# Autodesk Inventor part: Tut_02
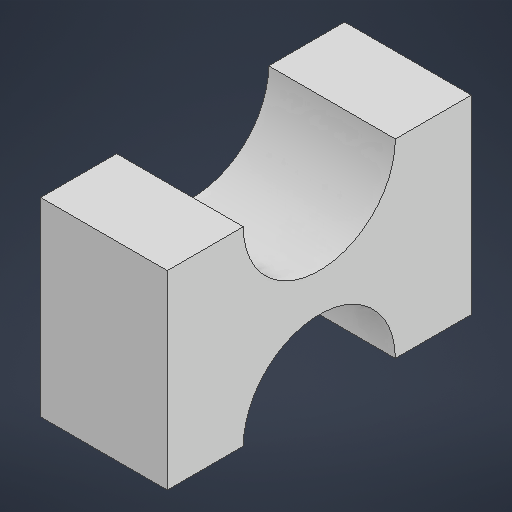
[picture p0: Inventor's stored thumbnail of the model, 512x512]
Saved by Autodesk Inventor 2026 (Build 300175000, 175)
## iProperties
Created: 2022-07
Part Number: Tut_02
Material: Generic
Document SubType Name: Modeling
Designer: LENOVO-CADCIM
Density: 1 g/cm^3
Appearance: Default
Author: LENOVO-CADCIM
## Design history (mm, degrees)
sketch "Sketch5"
  geometry: L1 (0, 0)-(0, 12); L2 (0, 0)-(12, 0); L3 (0, 0)-(0, -12); L4 (0, 12)-(0, 24); L5 (0, 12)-(12, 12); L6 (0, 24)-(-30, 24); L7 (-30, 24)-(-30, 12); L8 (-30, 12)-(-30, -12); L9 (-30, 12)-(-6, 12); L10 (-30, -12)-(-30, -24); L11 (-30, -12)-(-18, -12); L12 (-30, -24)-(0, -24); L13 (0, -24)-(0, -12); L14 (0, -24)-(12, -24); A1 r 12 centre (0, 0) between (0, 12) and (0, -12); A2 r 12 centre (-30, 0) between (-30, -12) and (-30, 12); 1 further point
  constraints: 28 end point, 8 perpendicular, 5 horizontal, 4 point on circle, 2 centre point, 2 vertical, 1 coincident
  dimensions: "d0" = 12 radius of A1; "d1" = 90 deg angle of L2 L1; "d2" = 180 deg angle of L3 L1; "d3" = 12 distance of L1.end L4.end; "d4" = 90 deg angle of L5 L4 (derived); "d5" = 30 distance of L4.end L6.end; "d6" = 90 deg angle of L6 L4 (derived); "d7" = 12 distance of L6.end L7.end; "d8" = 90 deg angle of L7 L6 (derived); "d9" = 24 distance of L7.end L8.end; "d10" = 90 deg angle of L8 L9; "d11" = 12 radius of A2; "d12" = 12 distance of L8.end L10.end; "d13" = 90 deg angle of L10 L11 (derived); "d14" = 30 distance of L10.end L12.end; "d15" = 90 deg angle of L12 L10 (derived); "d16" = 12 distance of L12.end L3.end (derived); "d17" = 90 deg angle of L14 L13 (derived)
extrude "Extrusion1" new body sketch "Sketch5" distance "d18" = 20; taper "d19" = 0 deg
body "Solid1"
